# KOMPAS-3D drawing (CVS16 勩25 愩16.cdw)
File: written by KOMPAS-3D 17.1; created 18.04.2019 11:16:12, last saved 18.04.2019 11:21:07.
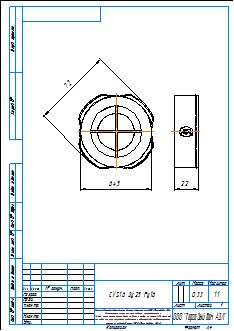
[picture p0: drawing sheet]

Sheet 1: A4, portrait

Title block, sheet 1: name: CVS16 Ду25 Ру16; material: Внимание! Данный продукт является объектом авторского права ООО «Торговый Дом АДЛ». / Запрещается изменение, копирование, распространение / (в том числе путем копирования на другие сайты и ресурсы в Интернете) / или любое иное использование информации и объектов без предварительного / согласия правообладателя (ООО «Торговый Дом АДЛ»).; mass: 0,33; sheets: 1; organisation: ООО "Торговый дом АДЛ"; sheet format: A4; stored path: \\adlc.lan\data\АДЛ_ПКД\3D-модели\ADL production\Клапаны обратные ГРАНЛОК\CVS16\KOMPAS 2D\CVS16 Ду25 Ру16.cdw

Views: Вид 1, Проекционный вид 2
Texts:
  user
Dimensions and other numbers on the sheet: 72; 64,5; 22; 1:1; 1; 0,33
